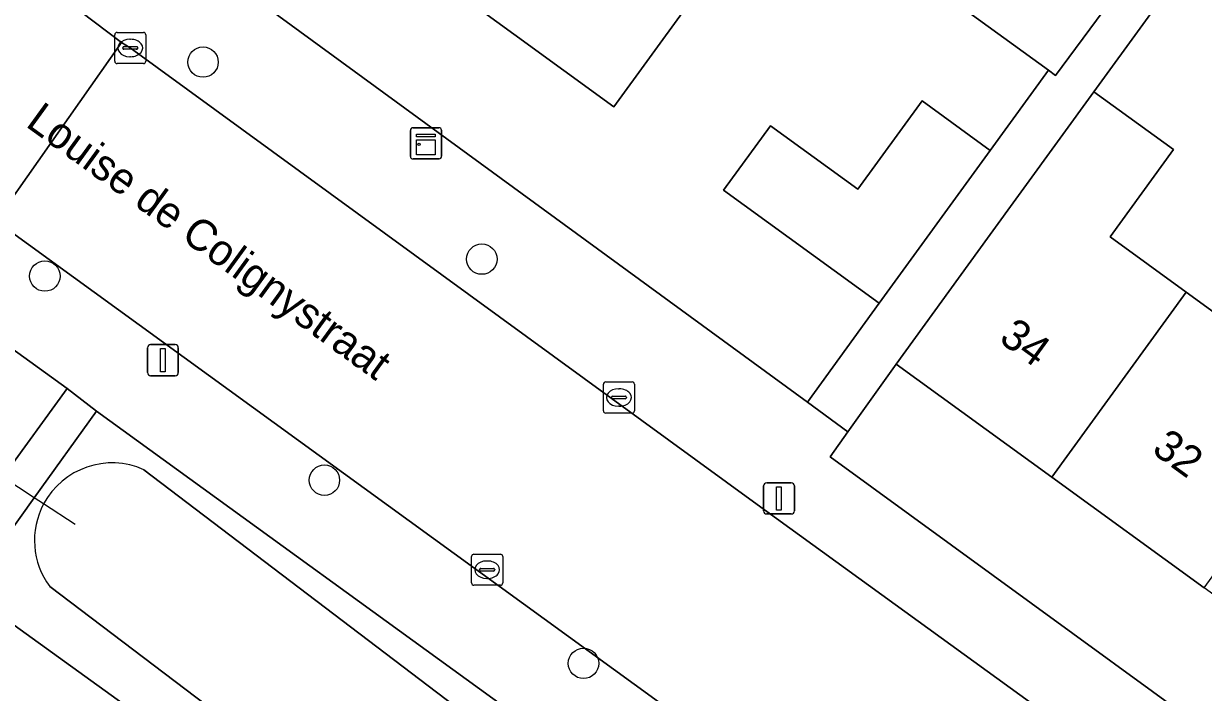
# Model space of a CAD drawing. Extents: x 159674 to 160531, y 382172 to 382904.
# Drawn here: x 160062.61 to 160100.56, y 382505.65 to 382527.16 of the extents above; entities that cross this region are included whole.
import ezdxf

# ---------------------------------------------------------------- set-up
doc = ezdxf.new("R2010")
doc.units = 0
for name, color, linetype in [('IMGEO_Boom', 7, 'Continuous'), ('IMGEO_Duiker', 7, 'Continuous'), ('IMGEO_Erf', 7, 'Continuous'), ('IMGEO_Groenvoorziening', 7, 'Continuous'), ('IMGEO_Kast', 7, 'Continuous'), ('IMGEO_Kolk', 7, 'Continuous'), ('IMGEO_Lichtmast', 7, 'Continuous'), ('IMGEO_Openbare_ruimte_label', 7, 'Continuous'), ('IMGEO_Pand', 7, 'Continuous'), ('IMGEO_Pand_nummerreeks', 7, 'Continuous'), ('IMGEO_Rijbaan_lokaal_open', 7, 'Continuous'), ('IMGEO_Voetpad_open', 7, 'Continuous'), ('IMGEO_Waterloop', 7, 'Continuous')]:
    doc.layers.add(name, color=color, linetype=linetype)

msp = doc.modelspace()

# ---------------------------------------------------------------- linework, layer by layer
at = {"layer": 'IMGEO_Boom'}
for centre in [(160068.381, 382525.919), (160077.349, 382519.584), (160063.294, 382519.039), (160072.286, 382512.476), (160080.62, 382506.587)]:
    msp.add_circle(centre, 0.489, dxfattribs=at)
at = {"layer": 'IMGEO_Duiker'}
msp.add_lwpolyline([(160064.27, 382511.047), (160063.253, 382511.711), (160062.952, 382511.908), (160061.941, 382512.569), (160061.175, 382513.07), (160060.634, 382513.423)], dxfattribs=at)
at = {"layer": 'IMGEO_Erf'}
for points in [[(160099.269, 382548.826), (160096.071, 382551.151), (160092.496, 382546.232), (160095.042, 382544.381), (160091.565, 382539.597), (160089.018, 382541.448), (160085.42, 382536.499), (160081.824, 382531.551), (160085.04, 382529.214), (160081.597, 382524.477), (160078.381, 382526.815), (160072.249, 382531.273), (160075.691, 382536.008), (160079.288, 382540.956), (160082.886, 382545.905), (160086.364, 382550.69), (160089.94, 382555.608), (160093.458, 382560.448), (160097.119, 382565.484), (160103.251, 382561.027), (160099.59, 382555.99), (160102.783, 382553.66)], [(160105.475, 382505.466), (160100.581, 382509.018), (160095.688, 382512.57), (160090.673, 382516.21), (160089.124, 382514.036), (160088.55, 382513.229), (160106.723, 382500), (160122.995, 382488.155), (160124.011, 382489.563), (160125.171, 382491.169), (160120.154, 382494.811), (160115.26, 382498.363), (160113.005, 382500), (160110.368, 382501.914)]]:
    msp.add_lwpolyline(points, close=True, dxfattribs=at)
for points in [[(160066.763, 382530.365), (160087.821, 382514.988), (160090.131, 382518.165), (160085.126, 382521.804), (160086.631, 382523.874), (160089.441, 382521.831), (160091.507, 382524.672), (160093.702, 382523.077), (160095.576, 382525.656), (160090.568, 382529.296), (160092.172, 382531.385), (160097.103, 382527.733), (160097.235, 382527.911), (160090.777, 382532.632), (160094.387, 382537.572), (160095.808, 382536.513), (160097.141, 382538.309), (160102.285, 382534.528), (160106.42, 382540.296)], [(160103.851, 382534.341), (160097.038, 382524.967), (160099.595, 382523.109), (160097.556, 382520.304), (160100.009, 382518.521), (160104.902, 382514.966)]]:
    msp.add_lwpolyline(points, dxfattribs=at)
at = {"layer": 'IMGEO_Groenvoorziening'}
for points in [[(160064.007, 382515.422), (160059.119, 382518.953), (160056.953, 382518.389), (160056.45, 382517.716), (160054.947, 382515.702), (160054.359, 382516.125), (160052.266, 382513.231), (160052.857, 382512.796), (160047.971, 382506.042), (160047.498, 382506.461), (160046.092, 382504.454), (160046.544, 382504.014), (160045.003, 382501.928), (160051.006, 382497.467), (160061.941, 382512.569)], [(160077.73, 382501.83), (160079.416, 382504.209), (160064.955, 382514.699), (160062.952, 382511.908), (160060.796, 382508.902), (160068.355, 382503.451), (160074.3, 382499.148), (160074.062, 382498.749), (160075.053, 382498.052), (160077.687, 382501.769)]]:
    msp.add_lwpolyline(points, close=True, dxfattribs=at)
for points in [[(160066.48, 382512.812), (160076.472, 382505.222)], [(160073.513, 382501.441), (160063.45, 382509.055)]]:
    msp.add_lwpolyline(points, dxfattribs=at)
for centre, radius, start, end in [((160065.455, 382510.537), 2.495, 65.7428, 151.9348), ((160065.453, 382510.539), 2.493, 151.95, 216.5339)]:
    msp.add_arc(centre, radius, start, end, dxfattribs=at)
at = {"layer": 'IMGEO_Kast'}
for p, q in [((160075.052, 382522.883), (160075.052, 382523.724)), ((160075.052, 382523.724), (160075.052, 382522.883)), ((160075.127, 382523.808), (160075.968, 382523.808)), ((160075.968, 382523.808), (160075.127, 382523.808)), ((160076.052, 382523.733), (160076.052, 382522.892)), ((160076.052, 382522.892), (160076.052, 382523.733)), ((160075.977, 382522.808), (160075.136, 382522.808)), ((160075.136, 382522.808), (160075.977, 382522.808))]:
    msp.add_line(p, q, dxfattribs=at)
for points in [[(160075.247, 382523.598), (160075.847, 382523.598), (160075.847, 382523.513), (160075.247, 382523.513), (160075.247, 382523.598)], [(160075.247, 382523.423), (160075.847, 382523.423), (160075.847, 382522.934), (160075.247, 382522.934), (160075.247, 382523.423)]]:
    msp.add_lwpolyline(points, dxfattribs=at)
msp.add_circle((160075.331, 382523.272), 0.0377, dxfattribs=at)
for centre, start, end in [((160075.13, 382523.73), 92.4484, 184.2845), ((160075.13, 382523.73), 92.4484, 184.2845), ((160075.974, 382523.73), 2.4484, 94.2845), ((160075.974, 382523.73), 2.4484, 94.2845), ((160075.13, 382522.886), 182.4484, 274.2845), ((160075.13, 382522.886), 182.4484, 274.2845), ((160075.974, 382522.886), 272.4484, 4.2845), ((160075.974, 382522.886), 272.4484, 4.2845)]:
    msp.add_arc(centre, 0.0779, start, end, dxfattribs=at)
at = {"layer": 'IMGEO_Kolk'}
for p, q in [((160065.54, 382525.947), (160065.54, 382526.799)), ((160065.615, 382526.873), (160066.467, 382526.873)), ((160066.541, 382526.799), (160066.541, 382525.947)), ((160065.799, 382526.367), (160065.799, 382526.379)), ((160066.237, 382526.33), (160065.839, 382526.33)), ((160065.842, 382526.416), (160066.24, 382526.416)), ((160066.028, 382526.653), (160066.053, 382526.653)), ((160066.283, 382526.379), (160066.283, 382526.367)), ((160066.051, 382526.093), (160066.026, 382526.093)), ((160066.467, 382525.873), (160065.615, 382525.873)), ((160081.258, 382514.708), (160081.258, 382515.56)), ((160081.333, 382515.634), (160082.185, 382515.634)), ((160081.746, 382515.414), (160081.771, 382515.414)), ((160082.259, 382515.56), (160082.259, 382514.708)), ((160081.517, 382515.128), (160081.517, 382515.14)), ((160081.955, 382515.091), (160081.557, 382515.091)), ((160081.56, 382515.177), (160081.958, 382515.177)), ((160082.001, 382515.14), (160082.001, 382515.128)), ((160082.185, 382514.634), (160081.333, 382514.634)), ((160081.769, 382514.854), (160081.744, 382514.854)), ((160077.02, 382509.172), (160077.02, 382510.024)), ((160077.095, 382510.098), (160077.947, 382510.098)), ((160078.021, 382510.024), (160078.021, 382509.172)), ((160077.279, 382509.592), (160077.279, 382509.604)), ((160077.322, 382509.641), (160077.72, 382509.641)), ((160077.508, 382509.878), (160077.533, 382509.878)), ((160077.763, 382509.604), (160077.763, 382509.592)), ((160077.717, 382509.555), (160077.319, 382509.555)), ((160077.531, 382509.318), (160077.506, 382509.318)), ((160077.947, 382509.098), (160077.095, 382509.098))]:
    msp.add_line(p, q, dxfattribs=at)
for points in [[(160065.54, 382525.947), (160065.54, 382526.799)], [(160065.615, 382526.873), (160066.467, 382526.873)], [(160066.541, 382526.799), (160066.541, 382525.947)], [(160066.467, 382525.873), (160065.615, 382525.873)], [(160081.258, 382514.708), (160081.258, 382515.56)], [(160081.333, 382515.634), (160082.185, 382515.634)], [(160082.259, 382515.56), (160082.259, 382514.708)], [(160082.185, 382514.634), (160081.333, 382514.634)], [(160077.02, 382509.172), (160077.02, 382510.024)], [(160077.095, 382510.098), (160077.947, 382510.098)], [(160078.021, 382510.024), (160078.021, 382509.172)], [(160077.947, 382509.098), (160077.095, 382509.098)]]:
    msp.add_lwpolyline(points, dxfattribs=at)
for centre, radius, start, end in [((160065.617, 382526.797), 0.0765, 91.552, 178.448), ((160065.617, 382526.797), 0.0765, 91.552, 178.448), ((160066.465, 382526.797), 0.0765, 1.552, 88.448), ((160066.465, 382526.797), 0.0765, 1.552, 88.448), ((160065.839, 382526.376), 0.0403, 85.8775, 175.7526), ((160065.836, 382526.366), 0.0366, 178.938, 274.7102), ((160066.24, 382526.373), 0.043, 264.8664, 352.4533), ((160066.244, 382526.378), 0.0386, 1.7309, 96.639), ((160065.617, 382525.949), 0.0765, 181.552, 268.448), ((160065.617, 382525.949), 0.0765, 181.552, 268.448), ((160066.465, 382525.949), 0.0765, 271.552, 358.448), ((160066.465, 382525.949), 0.0765, 271.552, 358.448), ((160081.335, 382515.558), 0.0765, 91.552, 178.448), ((160081.335, 382515.558), 0.0765, 91.552, 178.448), ((160082.183, 382515.558), 0.0765, 1.552, 88.448), ((160082.183, 382515.558), 0.0765, 1.552, 88.448), ((160081.557, 382515.137), 0.0403, 85.8775, 175.7526), ((160081.554, 382515.127), 0.0366, 178.938, 274.7102), ((160081.958, 382515.134), 0.043, 264.8664, 352.4533), ((160081.962, 382515.139), 0.0386, 1.7309, 96.639), ((160081.335, 382514.71), 0.0765, 181.552, 268.448), ((160081.335, 382514.71), 0.0765, 181.552, 268.448), ((160082.183, 382514.71), 0.0765, 271.552, 358.448), ((160082.183, 382514.71), 0.0765, 271.552, 358.448), ((160077.097, 382510.022), 0.0765, 91.552, 178.448), ((160077.097, 382510.022), 0.0765, 91.552, 178.448), ((160077.945, 382510.022), 0.0765, 1.552, 88.448), ((160077.945, 382510.022), 0.0765, 1.552, 88.448), ((160077.319, 382509.601), 0.0403, 85.8775, 175.7526), ((160077.724, 382509.603), 0.0386, 1.7309, 96.639), ((160077.316, 382509.591), 0.0366, 178.938, 274.7102), ((160077.72, 382509.598), 0.043, 264.8664, 352.4533), ((160077.097, 382509.174), 0.0765, 181.552, 268.448), ((160077.097, 382509.174), 0.0765, 181.552, 268.448), ((160077.945, 382509.174), 0.0765, 271.552, 358.448), ((160077.945, 382509.174), 0.0765, 271.552, 358.448)]:
    msp.add_arc(centre, radius, start, end, dxfattribs=at)
for centre, major_axis, ratio, start_param, end_param in [((160066.027, 382526.373), (-0.387, 0.002), 0.722429, 4.712389, 7.853982), ((160066.052, 382526.373), (-0.39, 0.002), 0.717154, 1.570796, 4.712389), ((160081.745, 382515.134), (-0.387, 0.002), 0.722429, 4.712389, 7.853982), ((160081.77, 382515.134), (-0.39, 0.002), 0.717154, 1.570796, 4.712389), ((160077.507, 382509.598), (-0.387, 0.002), 0.722429, 4.712389, 7.853982), ((160077.532, 382509.598), (-0.39, 0.002), 0.717154, 1.570796, 4.712389)]:
    msp.add_ellipse(centre, major_axis=major_axis, ratio=ratio, start_param=start_param, end_param=end_param, dxfattribs=at)
at = {"layer": 'IMGEO_Lichtmast'}
for p, q in [((160066.695, 382516.836), (160067.485, 382516.836)), ((160067.485, 382516.836), (160066.695, 382516.836)), ((160066.595, 382515.936), (160066.595, 382516.736)), ((160066.595, 382516.736), (160066.595, 382515.936)), ((160067.585, 382516.736), (160067.585, 382515.936)), ((160067.585, 382515.936), (160067.585, 382516.736)), ((160067.485, 382515.836), (160066.695, 382515.836)), ((160066.695, 382515.836), (160067.485, 382515.836)), ((160086.412, 382511.49), (160086.412, 382512.29)), ((160086.412, 382512.29), (160086.412, 382511.49)), ((160086.512, 382512.39), (160087.302, 382512.39)), ((160087.302, 382512.39), (160086.512, 382512.39)), ((160087.402, 382512.29), (160087.402, 382511.49)), ((160087.402, 382511.49), (160087.402, 382512.29)), ((160087.302, 382511.39), (160086.512, 382511.39)), ((160086.512, 382511.39), (160087.302, 382511.39))]:
    msp.add_line(p, q, dxfattribs=at)
for points in [[(160067.015, 382516.711), (160067.165, 382516.711), (160067.165, 382515.961), (160067.015, 382515.961), (160067.015, 382516.711)], [(160086.832, 382512.265), (160086.982, 382512.265), (160086.982, 382511.515), (160086.832, 382511.515), (160086.832, 382512.265)]]:
    msp.add_lwpolyline(points, dxfattribs=at)
for centre, start, end in [((160066.695, 382516.736), 90, 180), ((160066.695, 382516.736), 90, 180), ((160067.485, 382516.736), 0, 90), ((160067.485, 382516.736), 360, 90), ((160066.695, 382515.936), 180, 270), ((160066.695, 382515.936), 180, 270), ((160067.485, 382515.936), 270, 0), ((160067.485, 382515.936), 270, 0), ((160086.512, 382512.29), 90, 180), ((160086.512, 382512.29), 90, 180), ((160087.302, 382512.29), 0, 90), ((160087.302, 382512.29), 360, 90), ((160086.512, 382511.49), 180, 270), ((160086.512, 382511.49), 180, 270), ((160087.302, 382511.49), 270, 0), ((160087.302, 382511.49), 270, 0)]:
    msp.add_arc(centre, 0.1, start, end, dxfattribs=at)
at = {"layer": 'IMGEO_Pand'}
for points in [[(160081.824, 382531.551), (160075.691, 382536.008), (160072.249, 382531.273), (160078.381, 382526.815), (160081.597, 382524.477), (160085.04, 382529.214)], [(160092.172, 382531.385), (160090.568, 382529.296), (160095.576, 382525.656), (160095.8, 382525.493), (160097.338, 382527.559), (160097.103, 382527.733)], [(160095.688, 382512.57), (160100.009, 382518.521), (160097.556, 382520.304), (160099.595, 382523.109), (160097.038, 382524.967), (160093.613, 382520.255), (160090.673, 382516.21)], [(160090.131, 382518.165), (160093.702, 382523.077), (160091.507, 382524.672), (160089.441, 382521.831), (160086.631, 382523.874), (160085.126, 382521.804)], [(160095.688, 382512.57), (160100.581, 382509.018), (160104.902, 382514.966), (160100.009, 382518.521)], [(160060.796, 382508.902), (160060.677, 382508.988), (160060.489, 382508.727), (160060.579, 382508.662), (160057.526, 382504.439), (160057.437, 382504.503), (160057.344, 382504.374), (160065.02, 382498.831), (160065.126, 382498.977), (160065.037, 382499.042), (160068.076, 382503.253), (160068.166, 382503.189), (160068.355, 382503.451)]]:
    msp.add_lwpolyline(points, close=True, dxfattribs=at)
at = {"layer": 'IMGEO_Rijbaan_lokaal_open'}
for points in [[(160060.275, 382521.826), (160061.728, 382520.822), (160065.761, 382526.548), (160064.445, 382527.55)], [(160066.041, 382526.373), (160065.761, 382526.548), (160061.728, 382520.822), (160061.99, 382520.627), (160135.135, 382467.543), (160161.419, 382448.379)], [(160171.029, 382450.249), (160148.312, 382466.705), (160086.083, 382511.782), (160066.041, 382526.373)]]:
    msp.add_lwpolyline(points, dxfattribs=at)
at = {"layer": 'IMGEO_Voetpad_open'}
for points in [[(160100.846, 382532.851), (160097.235, 382527.911), (160097.103, 382527.733), (160097.338, 382527.559), (160095.8, 382525.493), (160095.576, 382525.656), (160093.702, 382523.077), (160090.131, 382518.165), (160087.821, 382514.988), (160089.124, 382514.036), (160090.673, 382516.21), (160093.613, 382520.255), (160097.038, 382524.967), (160103.851, 382534.341)], [(160088.55, 382513.229), (160089.124, 382514.036), (160087.821, 382514.988), (160066.763, 382530.365)], [(160064.445, 382527.55), (160065.761, 382526.548), (160066.041, 382526.373), (160086.083, 382511.782), (160148.312, 382466.705), (160171.029, 382450.249)], [(160161.419, 382448.379), (160135.135, 382467.543), (160061.99, 382520.627)], [(160059.119, 382518.953), (160064.007, 382515.422), (160064.955, 382514.699), (160079.416, 382504.209)], [(160060.796, 382508.902), (160062.952, 382511.908), (160064.955, 382514.699), (160064.007, 382515.422), (160061.941, 382512.569)], [(160174.179, 382449.327), (160174.199, 382452.933), (160173.407, 382451.842), (160162.122, 382460.043), (160162.914, 382461.134), (160161.521, 382462.147), (160161.358, 382462.265), (160125.316, 382488.609), (160127.653, 382491.801), (160126.342, 382492.78), (160125.171, 382491.169), (160124.011, 382489.563), (160122.995, 382488.155), (160106.723, 382500), (160088.55, 382513.229)]]:
    msp.add_lwpolyline(points, dxfattribs=at)
at = {"layer": 'IMGEO_Waterloop'}
for points in [[(160076.472, 382505.222), (160066.48, 382512.812)], [(160063.45, 382509.055), (160073.513, 382501.441)]]:
    msp.add_lwpolyline(points, dxfattribs=at)
for centre, radius, start, end in [((160065.455, 382510.537), 2.495, 65.7428, 151.9348), ((160065.453, 382510.539), 2.493, 151.95, 216.5339)]:
    msp.add_arc(centre, radius, start, end, dxfattribs=at)

# ---------------------------------------------------------------- texts
at = {"layer": 'IMGEO_Openbare_ruimte_label'}
msp.add_text('Louise de Colignystraat', height=1, rotation=323.9895, dxfattribs=at).set_placement((160062.641, 382523.876))
at = {"layer": 'IMGEO_Pand_nummerreeks'}
for s, p in [('34', (160093.943, 382516.95)), ('32', (160098.858, 382513.382))]:
    msp.add_text(s, height=1, rotation=324.0254, dxfattribs=at).set_placement(p)

doc.saveas('drawing.dxf')
